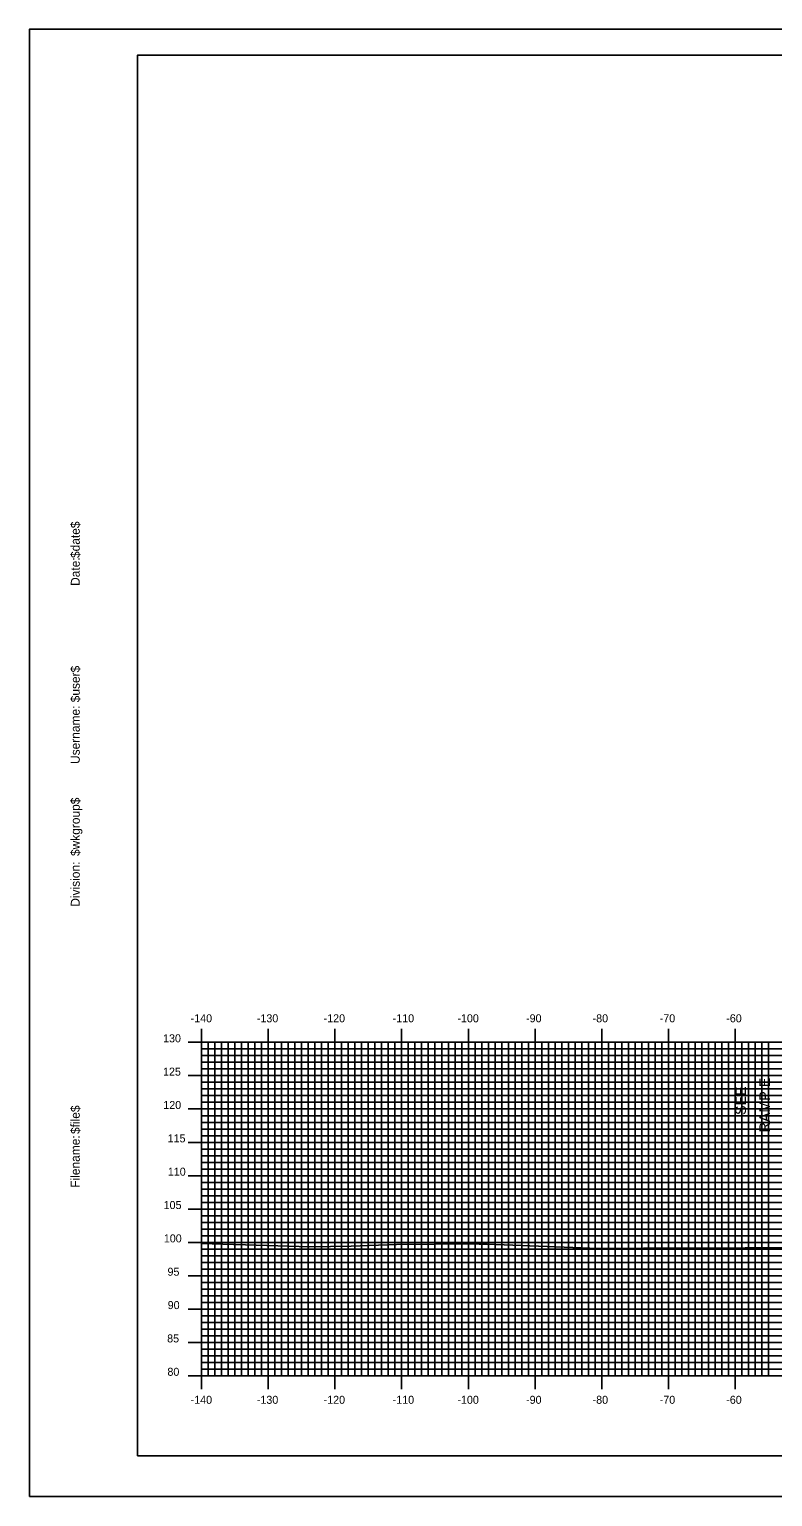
# Model space of a CAD drawing. Extents: x -695 to -352, y -1658 to -1438.
# Drawn here: x -695.2 to -583.8, y -1657.7 to -1437.7 of the extents above; entities that cross this region are included whole.
import ezdxf

# ---------------------------------------------------------------- set-up
doc = ezdxf.new("R2010")
doc.units = 0
for name, color, linetype in [('ANNOTATION', 7, 'Continuous'), ('BORDER', 7, 'Continuous'), ('H_V ANNOTATION', 7, 'Continuous'), ('MAJOR', 7, 'Continuous'), ('MINOR', 7, 'Continuous'), ('PLOT BOUNDARY', 7, 'Continuous'), ('S_Roadway_Centerline', 7, 'Continuous')]:
    doc.layers.add(name, color=color, linetype=linetype)

msp = doc.modelspace()

# ---------------------------------------------------------------- linework, layer by layer
at = {"layer": 'BORDER'}
msp.add_lwpolyline([(-679, -1651.6), (-359, -1651.6), (-359, -1441.6), (-679, -1441.6)], close=True, dxfattribs=at)
at = {"layer": 'MAJOR'}
for p, q in [((-669.4, -1587.6), (-669.4, -1589.6)), ((-659.4, -1587.6), (-659.4, -1589.6)), ((-649.4, -1587.6), (-649.4, -1589.6)), ((-639.4, -1587.6), (-639.4, -1589.6)), ((-629.4, -1587.6), (-629.4, -1589.6)), ((-619.4, -1587.6), (-619.4, -1589.6)), ((-609.4, -1587.6), (-609.4, -1589.6)), ((-599.4, -1587.6), (-599.4, -1589.6)), ((-589.4, -1587.6), (-589.4, -1589.6)), ((-671.41, -1589.6), (-669.4, -1589.6)), ((-669.4, -1589.6), (-389.4, -1589.6)), ((-669.4, -1639.6), (-669.4, -1589.6)), ((-669.4, -1639.6), (-669.4, -1589.6)), ((-669.4, -1589.6), (-389.4, -1589.6)), ((-659.4, -1639.6), (-659.4, -1589.6)), ((-649.4, -1639.6), (-649.4, -1589.6)), ((-639.4, -1639.6), (-639.4, -1589.6)), ((-629.4, -1639.6), (-629.4, -1589.6)), ((-619.4, -1639.6), (-619.4, -1589.6)), ((-609.4, -1639.6), (-609.4, -1589.6)), ((-599.4, -1639.6), (-599.4, -1589.6)), ((-589.4, -1639.6), (-589.4, -1589.6)), ((-671.41, -1594.6), (-669.4, -1594.6)), ((-669.4, -1594.6), (-389.4, -1594.6)), ((-671.41, -1599.6), (-669.4, -1599.6)), ((-669.4, -1599.6), (-389.4, -1599.6)), ((-671.41, -1604.6), (-669.4, -1604.6)), ((-669.4, -1604.6), (-389.4, -1604.6)), ((-671.41, -1609.6), (-669.4, -1609.6)), ((-669.4, -1609.6), (-389.4, -1609.6)), ((-671.41, -1614.6), (-669.4, -1614.6)), ((-669.4, -1614.6), (-389.4, -1614.6)), ((-671.41, -1619.6), (-669.4, -1619.6)), ((-669.4, -1619.6), (-389.4, -1619.6)), ((-671.41, -1624.6), (-669.4, -1624.6)), ((-669.4, -1624.6), (-389.4, -1624.6)), ((-671.41, -1629.6), (-669.4, -1629.6)), ((-669.4, -1629.6), (-389.4, -1629.6)), ((-671.41, -1634.6), (-669.4, -1634.6)), ((-669.4, -1634.6), (-389.4, -1634.6)), ((-671.41, -1639.6), (-669.4, -1639.6)), ((-669.4, -1639.6), (-389.4, -1639.6)), ((-669.4, -1639.6), (-389.4, -1639.6)), ((-669.4, -1641.61), (-669.4, -1639.6)), ((-659.4, -1641.61), (-659.4, -1639.6)), ((-649.4, -1641.61), (-649.4, -1639.6)), ((-639.4, -1641.61), (-639.4, -1639.6)), ((-629.4, -1641.61), (-629.4, -1639.6)), ((-619.4, -1641.61), (-619.4, -1639.6)), ((-609.4, -1641.61), (-609.4, -1639.6)), ((-599.4, -1641.61), (-599.4, -1639.6)), ((-589.4, -1641.61), (-589.4, -1639.6))]:
    msp.add_line(p, q, dxfattribs=at)
at = {"layer": 'MINOR'}
for p, q in [((-668.4, -1639.6), (-668.4, -1589.6)), ((-667.4, -1639.6), (-667.4, -1589.6)), ((-666.4, -1639.6), (-666.4, -1589.6)), ((-665.4, -1639.6), (-665.4, -1589.6)), ((-664.4, -1639.6), (-664.4, -1589.6)), ((-663.4, -1639.6), (-663.4, -1589.6)), ((-662.4, -1639.6), (-662.4, -1589.6)), ((-661.4, -1639.6), (-661.4, -1589.6)), ((-660.4, -1639.6), (-660.4, -1589.6)), ((-658.4, -1639.6), (-658.4, -1589.6)), ((-657.4, -1639.6), (-657.4, -1589.6)), ((-656.4, -1639.6), (-656.4, -1589.6)), ((-655.4, -1639.6), (-655.4, -1589.6)), ((-654.4, -1639.6), (-654.4, -1589.6)), ((-653.4, -1639.6), (-653.4, -1589.6)), ((-652.4, -1639.6), (-652.4, -1589.6)), ((-651.4, -1639.6), (-651.4, -1589.6)), ((-650.4, -1639.6), (-650.4, -1589.6)), ((-648.4, -1639.6), (-648.4, -1589.6)), ((-647.4, -1639.6), (-647.4, -1589.6)), ((-646.4, -1639.6), (-646.4, -1589.6)), ((-645.4, -1639.6), (-645.4, -1589.6)), ((-644.4, -1639.6), (-644.4, -1589.6)), ((-643.4, -1639.6), (-643.4, -1589.6)), ((-642.4, -1639.6), (-642.4, -1589.6)), ((-641.4, -1639.6), (-641.4, -1589.6)), ((-640.4, -1639.6), (-640.4, -1589.6)), ((-638.4, -1639.6), (-638.4, -1589.6)), ((-637.4, -1639.6), (-637.4, -1589.6)), ((-636.4, -1639.6), (-636.4, -1589.6)), ((-635.4, -1639.6), (-635.4, -1589.6)), ((-634.4, -1639.6), (-634.4, -1589.6)), ((-633.4, -1639.6), (-633.4, -1589.6)), ((-632.4, -1639.6), (-632.4, -1589.6)), ((-631.4, -1639.6), (-631.4, -1589.6)), ((-630.4, -1639.6), (-630.4, -1589.6)), ((-628.4, -1639.6), (-628.4, -1589.6)), ((-627.4, -1639.6), (-627.4, -1589.6)), ((-626.4, -1639.6), (-626.4, -1589.6)), ((-625.4, -1639.6), (-625.4, -1589.6)), ((-624.4, -1639.6), (-624.4, -1589.6)), ((-623.4, -1639.6), (-623.4, -1589.6)), ((-622.4, -1639.6), (-622.4, -1589.6)), ((-621.4, -1639.6), (-621.4, -1589.6)), ((-620.4, -1639.6), (-620.4, -1589.6)), ((-618.4, -1639.6), (-618.4, -1589.6)), ((-617.4, -1639.6), (-617.4, -1589.6)), ((-616.4, -1639.6), (-616.4, -1589.6)), ((-615.4, -1639.6), (-615.4, -1589.6)), ((-614.4, -1639.6), (-614.4, -1589.6)), ((-613.4, -1639.6), (-613.4, -1589.6)), ((-612.4, -1639.6), (-612.4, -1589.6)), ((-611.4, -1639.6), (-611.4, -1589.6)), ((-610.4, -1639.6), (-610.4, -1589.6)), ((-608.4, -1639.6), (-608.4, -1589.6)), ((-607.4, -1639.6), (-607.4, -1589.6)), ((-606.4, -1639.6), (-606.4, -1589.6)), ((-605.4, -1639.6), (-605.4, -1589.6)), ((-604.4, -1639.6), (-604.4, -1589.6)), ((-603.4, -1639.6), (-603.4, -1589.6)), ((-602.4, -1639.6), (-602.4, -1589.6)), ((-601.4, -1639.6), (-601.4, -1589.6)), ((-600.4, -1639.6), (-600.4, -1589.6)), ((-598.4, -1639.6), (-598.4, -1589.6)), ((-597.4, -1639.6), (-597.4, -1589.6)), ((-596.4, -1639.6), (-596.4, -1589.6)), ((-595.4, -1639.6), (-595.4, -1589.6)), ((-594.4, -1639.6), (-594.4, -1589.6)), ((-593.4, -1639.6), (-593.4, -1589.6)), ((-592.4, -1639.6), (-592.4, -1589.6)), ((-591.4, -1639.6), (-591.4, -1589.6)), ((-590.4, -1639.6), (-590.4, -1589.6)), ((-588.4, -1639.6), (-588.4, -1589.6)), ((-587.4, -1639.6), (-587.4, -1589.6)), ((-586.4, -1639.6), (-586.4, -1589.6)), ((-585.4, -1639.6), (-585.4, -1589.6)), ((-584.4, -1639.6), (-584.4, -1589.6)), ((-669.4, -1590.6), (-389.4, -1590.6)), ((-669.4, -1590.6), (-667.4, -1590.6)), ((-669.4, -1591.6), (-389.4, -1591.6)), ((-669.4, -1591.6), (-667.4, -1591.6)), ((-669.4, -1592.6), (-389.4, -1592.6)), ((-669.4, -1592.6), (-667.4, -1592.6)), ((-669.4, -1593.6), (-389.4, -1593.6)), ((-669.4, -1593.6), (-667.4, -1593.6)), ((-669.4, -1595.6), (-389.4, -1595.6)), ((-669.4, -1595.6), (-667.4, -1595.6)), ((-669.4, -1596.6), (-389.4, -1596.6)), ((-669.4, -1596.6), (-667.4, -1596.6)), ((-669.4, -1597.6), (-389.4, -1597.6)), ((-669.4, -1597.6), (-667.4, -1597.6)), ((-669.4, -1598.6), (-389.4, -1598.6)), ((-669.4, -1598.6), (-667.4, -1598.6)), ((-669.4, -1600.6), (-389.4, -1600.6)), ((-669.4, -1600.6), (-667.4, -1600.6)), ((-669.4, -1601.6), (-389.4, -1601.6)), ((-669.4, -1601.6), (-667.4, -1601.6)), ((-669.4, -1602.6), (-389.4, -1602.6)), ((-669.4, -1602.6), (-667.4, -1602.6)), ((-669.4, -1603.6), (-389.4, -1603.6)), ((-669.4, -1603.6), (-667.4, -1603.6)), ((-669.4, -1605.6), (-389.4, -1605.6)), ((-669.4, -1605.6), (-667.4, -1605.6)), ((-669.4, -1606.6), (-389.4, -1606.6)), ((-669.4, -1606.6), (-667.4, -1606.6)), ((-669.4, -1607.6), (-389.4, -1607.6)), ((-669.4, -1607.6), (-667.4, -1607.6)), ((-669.4, -1608.6), (-389.4, -1608.6)), ((-669.4, -1608.6), (-667.4, -1608.6)), ((-669.4, -1610.6), (-389.4, -1610.6)), ((-669.4, -1610.6), (-667.4, -1610.6)), ((-669.4, -1611.6), (-389.4, -1611.6)), ((-669.4, -1611.6), (-667.4, -1611.6)), ((-669.4, -1612.6), (-389.4, -1612.6)), ((-669.4, -1612.6), (-667.4, -1612.6)), ((-669.4, -1613.6), (-389.4, -1613.6)), ((-669.4, -1613.6), (-667.4, -1613.6)), ((-669.4, -1615.6), (-389.4, -1615.6)), ((-669.4, -1615.6), (-667.4, -1615.6)), ((-669.4, -1616.6), (-389.4, -1616.6)), ((-669.4, -1616.6), (-667.4, -1616.6)), ((-669.4, -1617.6), (-389.4, -1617.6)), ((-669.4, -1617.6), (-667.4, -1617.6)), ((-669.4, -1618.6), (-389.4, -1618.6)), ((-669.4, -1618.6), (-667.4, -1618.6)), ((-669.4, -1620.6), (-389.4, -1620.6)), ((-669.4, -1620.6), (-667.4, -1620.6)), ((-669.4, -1621.6), (-389.4, -1621.6)), ((-669.4, -1621.6), (-667.4, -1621.6)), ((-669.4, -1622.6), (-389.4, -1622.6)), ((-669.4, -1622.6), (-667.4, -1622.6)), ((-669.4, -1623.6), (-389.4, -1623.6)), ((-669.4, -1623.6), (-667.4, -1623.6)), ((-669.4, -1625.6), (-389.4, -1625.6)), ((-669.4, -1625.6), (-667.4, -1625.6)), ((-669.4, -1626.6), (-389.4, -1626.6)), ((-669.4, -1626.6), (-667.4, -1626.6)), ((-669.4, -1627.6), (-389.4, -1627.6)), ((-669.4, -1627.6), (-667.4, -1627.6)), ((-669.4, -1628.6), (-389.4, -1628.6)), ((-669.4, -1628.6), (-667.4, -1628.6)), ((-669.4, -1630.6), (-389.4, -1630.6)), ((-669.4, -1630.6), (-667.4, -1630.6)), ((-669.4, -1631.6), (-389.4, -1631.6)), ((-669.4, -1631.6), (-667.4, -1631.6)), ((-669.4, -1632.6), (-389.4, -1632.6)), ((-669.4, -1632.6), (-667.4, -1632.6)), ((-669.4, -1633.6), (-389.4, -1633.6)), ((-669.4, -1633.6), (-667.4, -1633.6)), ((-669.4, -1635.6), (-389.4, -1635.6)), ((-669.4, -1635.6), (-667.4, -1635.6)), ((-669.4, -1636.6), (-389.4, -1636.6)), ((-669.4, -1636.6), (-667.4, -1636.6)), ((-669.4, -1637.6), (-389.4, -1637.6)), ((-669.4, -1637.6), (-667.4, -1637.6)), ((-669.4, -1638.6), (-389.4, -1638.6)), ((-669.4, -1638.6), (-667.4, -1638.6))]:
    msp.add_line(p, q, dxfattribs=at)
at = {"layer": 'PLOT BOUNDARY'}
msp.add_lwpolyline([(-695.19, -1657.72), (-355.19, -1657.72), (-355.19, -1437.72), (-695.19, -1437.72)], close=True, dxfattribs=at)
at = {"layer": 'S_Roadway_Centerline'}
msp.add_lwpolyline([(-669.4, -1619.75), (-664.61, -1619.9), (-664.46, -1619.9), (-664.39, -1619.9), (-653.18, -1620.25), (-646.95, -1620.17), (-640.18, -1619.94), (-628.43, -1619.8), (-627.8, -1619.87), (-626.58, -1619.85), (-609.88, -1620.5), (-596.44, -1620.44), (-592.39, -1620.49), (-587.91, -1620.43), (-572.61, -1620.39)], dxfattribs=at)

# ---------------------------------------------------------------- texts
at = {"layer": 'ANNOTATION'}
for s, p in [('SEE', (-587.79, -1600.5)), ('RAMP E', (-584.19, -1603.11))]:
    msp.add_text(s, height=1.6, rotation=90, dxfattribs=at).set_placement(p)
at = {"layer": 'BORDER'}
for s, p in [('$date$', (-687.64, -1516.99)), ('Date:', (-687.64, -1521.17)), ('$user$', (-687.64, -1538.62)), ('Username:', (-687.64, -1547.87)), ('$wkgroup$', (-687.64, -1561.67)), ('Division:', (-687.64, -1569.27)), ('$file$', (-687.64, -1603.35)), ('Filename:', (-687.64, -1611.41))]:
    msp.add_text(s, height=1.339, rotation=90, dxfattribs=at).set_placement(p)
at = {"layer": 'H_V ANNOTATION'}
for s, p in [('-140', (-671.02, -1586.6)), ('-130', (-661.1, -1586.6)), ('-120', (-651.09, -1586.6)), ('-110', (-640.74, -1586.6)), ('-100', (-631.04, -1586.6)), ('-90', (-620.75, -1586.6)), ('-80', (-610.78, -1586.6)), ('-70', (-600.72, -1586.6)), ('-60', (-590.75, -1586.6)), ('130', (-675.15, -1589.6)), ('125', (-675.16, -1594.6)), ('120', (-675.12, -1599.6)), ('115', (-674.47, -1604.6)), ('110', (-674.44, -1609.6)), ('105', (-675.07, -1614.6)), ('100', (-675.04, -1619.6)), ('95', (-674.49, -1624.6)), ('90', (-674.46, -1629.6)), ('85', (-674.54, -1634.6)), ('80', (-674.5, -1639.6)), ('-140', (-671.02, -1643.8)), ('-130', (-661.1, -1643.8)), ('-120', (-651.09, -1643.8)), ('-110', (-640.74, -1643.8)), ('-100', (-631.04, -1643.8)), ('-90', (-620.75, -1643.8)), ('-80', (-610.78, -1643.8)), ('-70', (-600.72, -1643.8)), ('-60', (-590.75, -1643.8))]:
    msp.add_text(s, height=1.2, dxfattribs=at).set_placement(p)
at = {"layer": 'MAJOR'}
msp.add_text('-', height=0.012, dxfattribs=at).set_placement((-669.41, -1639.6))

doc.saveas('drawing.dxf')
